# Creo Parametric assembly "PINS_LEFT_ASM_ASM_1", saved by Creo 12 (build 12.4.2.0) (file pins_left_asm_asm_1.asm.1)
Units: Custom; MM, KILOGRAM, SECS

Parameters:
  PTC_WM_ITERATION = "0"
  PTC_WM_VERSION = "-.0"
  PTC_WM_LIFECYCLE_STATE = "In Work"
  PTC_WM_LIFECYCLE = "MO_CADDocument"
  PTC_WM_CREATED_BY = "Maximilian Roepper (Z0017RMS: MO)"
  PTC_WM_CREATED_ON = "18-Sep-26 11:36:42 AM"
  PTC_WM_MODIFIED_BY = "Maximilian Roepper (Z0017RMS: MO)"
  PTC_WM_MODIFIED_ON = "18-Sep-26 11:36:46 AM"
  PDMLINKNUMBER = "PDM000071455196"
  PTC_WM_NUMBER = "PDM000071455196"

Other parameters: WEIGHT, WEIGHT_FACTOR, WEIGHT_ADD, MC_ERRORS, SUPPLIER

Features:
  1. coordinate system
  2. imported feature
  3. component "PIN_011_PRT_1"
  4. component "PIN_012_PRT_1"
  5. component "PIN_013_PRT_1"
  6. component "PIN_014_PRT_1"
  7. component "PIN_015_PRT_1"
  8. component "PIN_016_PRT_1"
  9. component "PIN_017_PRT_1"
  10. component "PIN_018_PRT_1"
  11. component "PIN_019_PRT_1"
  12. component "PIN_020_PRT_1"
  13. component "PIN_021_PRT_1"
  14. component "PIN_022_PRT_1"
  15. component "PIN_023_PRT_1"
  16. component "PIN_024_PRT_1"

Other named items: DRW_VIEW_ORG, ROUGH-GROB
